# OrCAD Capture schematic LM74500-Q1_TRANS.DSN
size E; title: LM74500-Q1: Low IQ Reverse Battery Protection Controller; rev: 1.0; note: Datasheet: SNOSDB7     EVM: PSIL144; note: Synchronous Step Down Converter
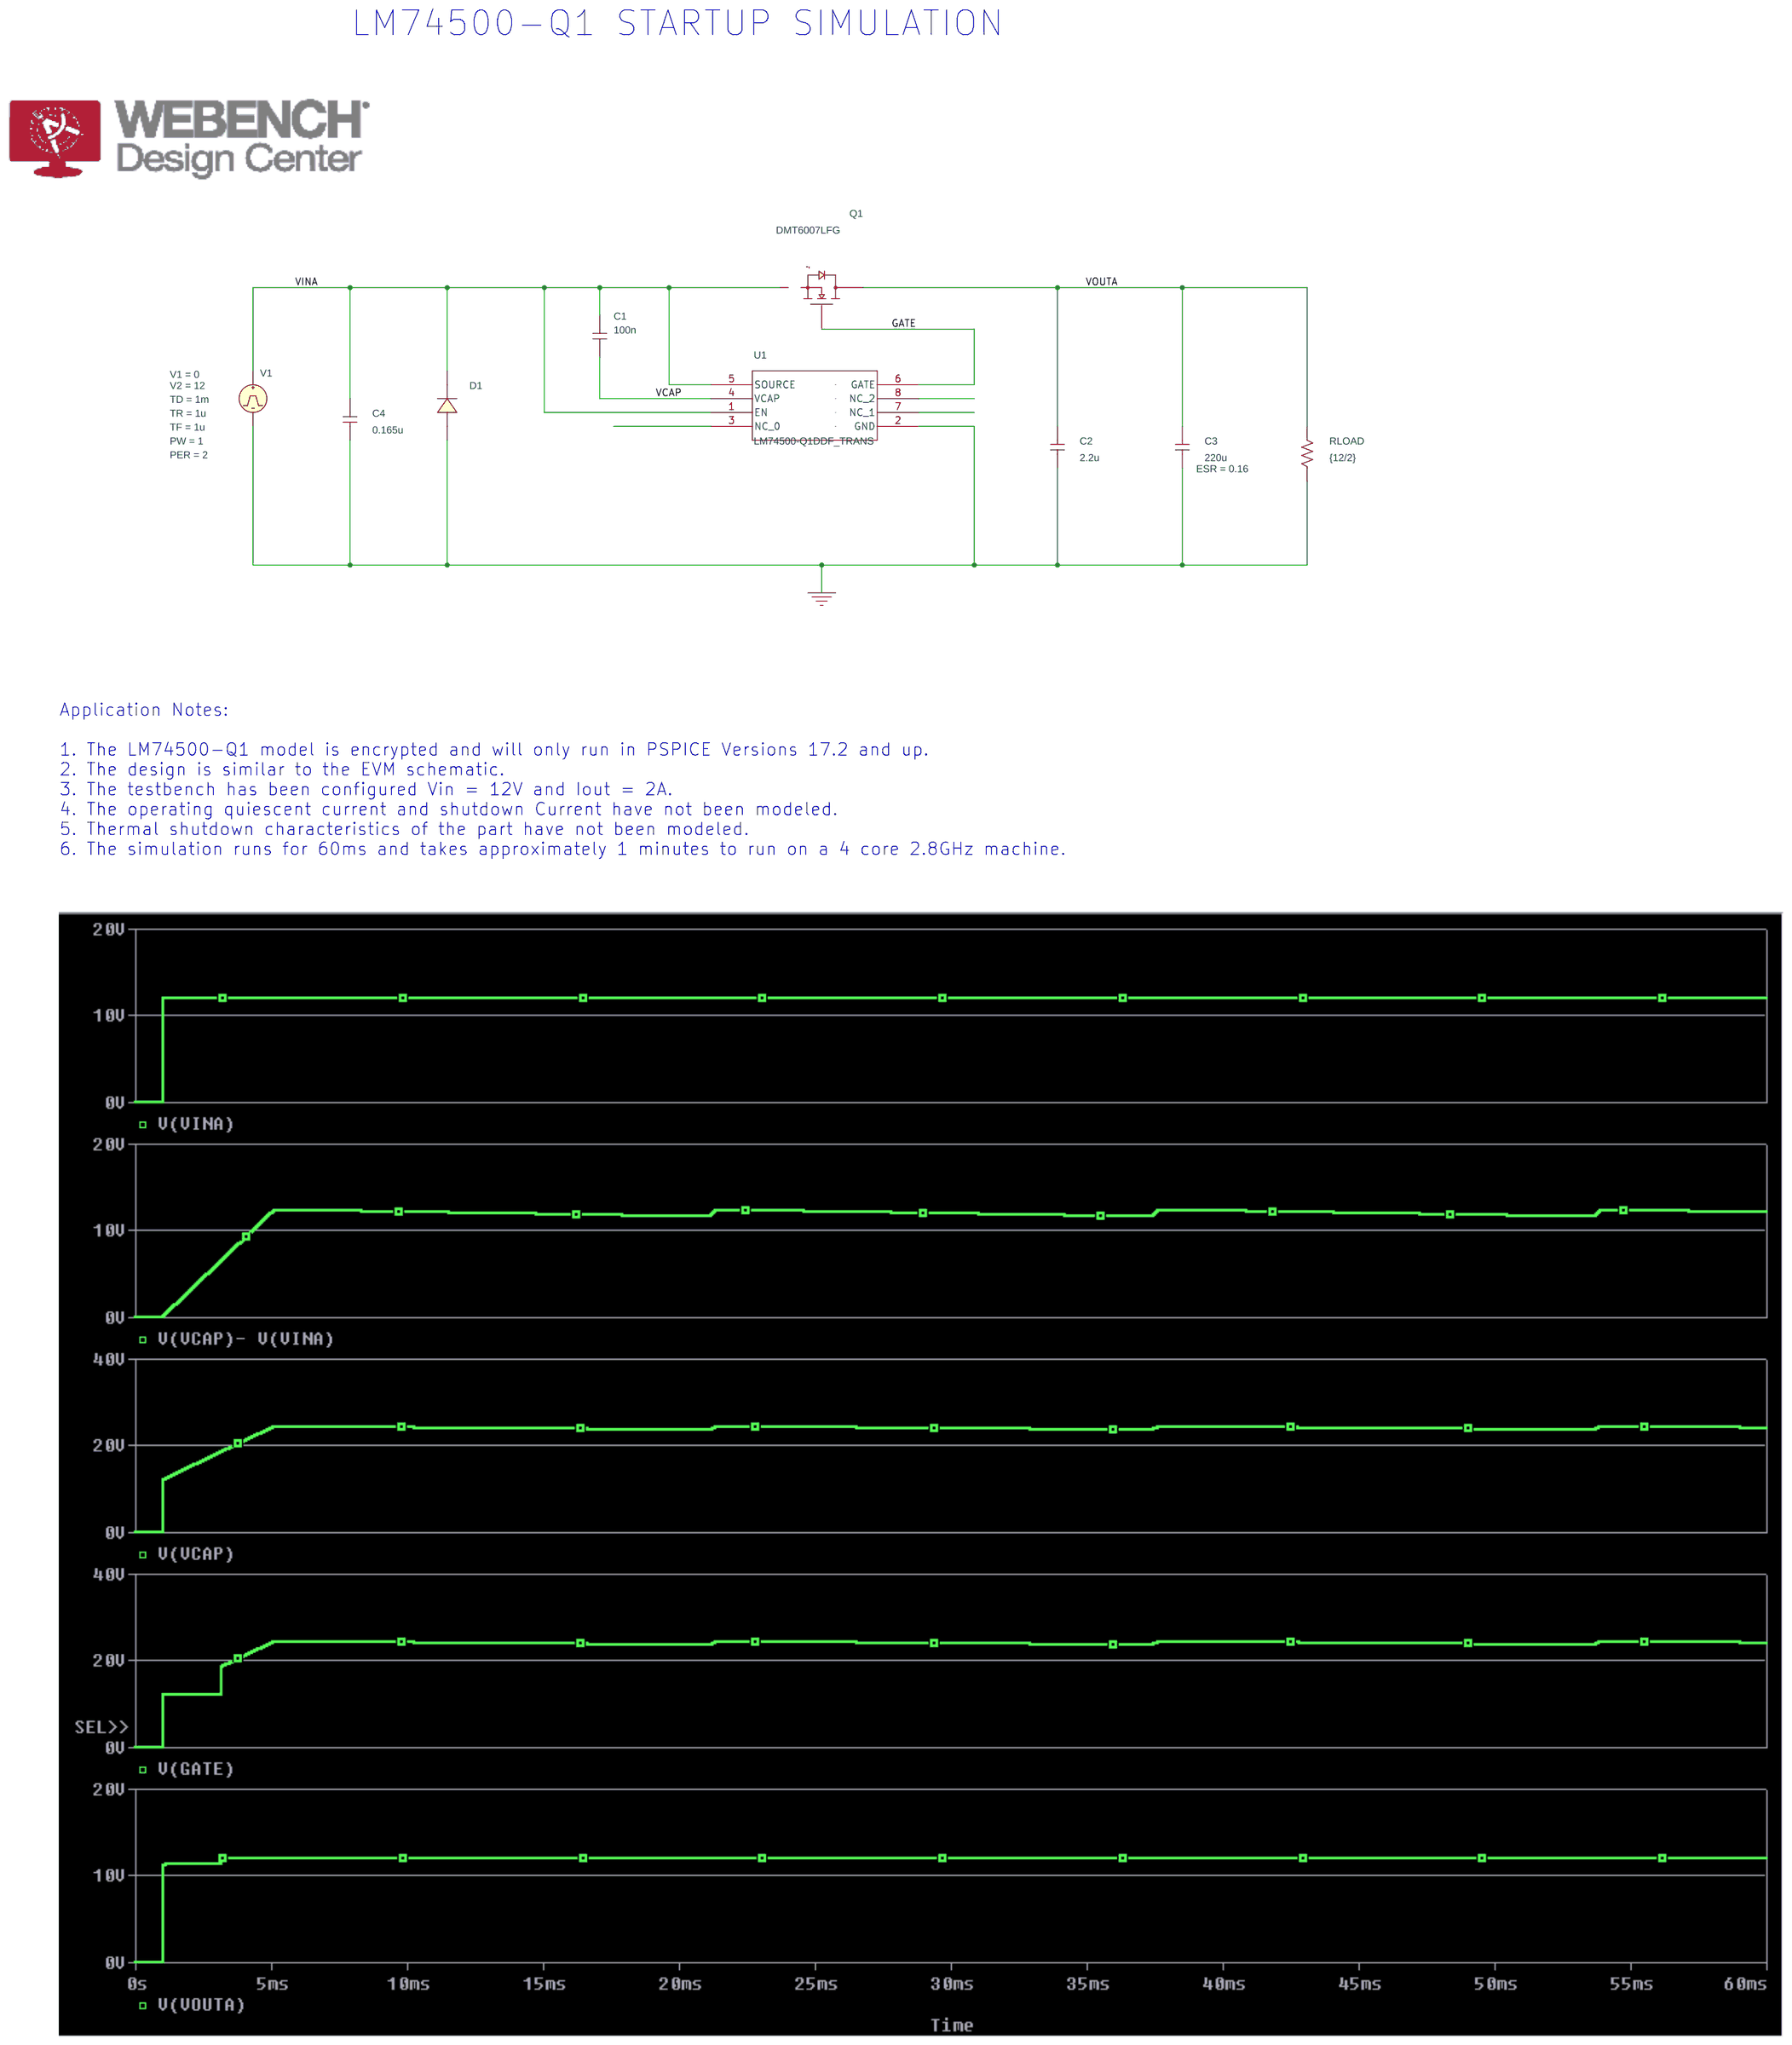
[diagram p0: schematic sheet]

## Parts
C1  100n  [RAD/CK05]
C2  2.2u  [RAD/CK05]
C3  220u  [RAD/CK05]
C4  0.165u  [RAD/CK05]
D1  SMBJ33A
Q1  DMT6007LFG
RLOAD  {12/2}  [AX/RC05]
U1  LM74500-Q1DDF_TRANS  [DDF0008A-IPC_A]
V1  VPULSE

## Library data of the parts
C1 C2 C4 = C
C3 = C: AppProp: InductiveSlave:;SRF:;PrevCap:220u;PrevESL:; ESR: 0.16
D1 = SMBJ33A
Q1 = CSD18540Q5B: PSpiceTemplate: X^@REFDES  %drain %gate %source @MODEL
RLOAD = R
U1 = LM74500-Q1DDF_TRANS
V1 = VPULSE: PER: 2; PW: 1; TD: 1m; TF: 1u; TR: 1u; V1: 0; V2: 12

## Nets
VINA: C1.2 C4.2 D1.1(C) Q1.source U1.1(EN) U1.5(SOURCE) V1.1(+)
0: C2.1 C3.1 C4.1 D1.2(A) RLOAD.1 U1.2(GND) V1.2(-)
GATE: Q1.gate U1.6(GATE)
VCAP: C1.1 U1.4(VCAP)
VOUTA: C2.2 C3.2 Q1.drain RLOAD.2

Not connected (* = marked no-connect by the designer): U1 3(NC_0) 7(NC_1) 8(NC_2)

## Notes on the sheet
- LM74500-Q1 STARTUP SIMULATION
- Application Notes:
  1. The LM74500-Q1 model is encrypted and will only run in PSPICE Versions 17.2 and up.
  2. The design is similar to the EVM schematic.
  3. The testbench has been configured Vin = 12V and Iout = 2A.
  4. The operating quiescent current and shutdown Current have not been modeled.
  5. Thermal shutdown characteristics of the part have not been modeled.
  6. The simulation runs for 60ms and takes approximately 1 minutes to run on a 4 core 2.8GHz machine.
